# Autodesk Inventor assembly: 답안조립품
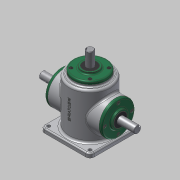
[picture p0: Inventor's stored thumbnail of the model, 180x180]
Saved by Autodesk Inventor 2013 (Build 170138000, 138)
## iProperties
Created: 2015-10
Part Number: 답안조립품
Document SubType Name: Assembly
Designer: user-11
Author: user-11
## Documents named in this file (14)
- C:\Users\user-11\Desktop\451007V1002\답안조립품.iam
- C:\Users\user-11\Desktop\451007V1002\본체.ipt
- C:\Users\user-11\Desktop\451007V1002\서브 베벨기어.ipt
- C:\Users\user-11\Desktop\451007V1002\서브 축.ipt
- 서브 축.ipt
- C:\Users\user-11\Desktop\451007V1002\오일실.ipt
- C:\Users\user-11\Desktop\451007V1002\커버.ipt
- C:\Users\user-11\Desktop\451007V1002\키 4x4.ipt
- C:\Users\user-11\Desktop\451007V1002\키 5x5.ipt
- C:\Users\user-11\Desktop\451007V1002\M4.ipt
- C:\Users\user-11\Desktop\451007V1002\메인 베벨기어.ipt
- C:\Users\user-11\Desktop\451007V1002\메인 축.ipt
- 메인 축.ipt
- C:\Users\user-11\Desktop\451007V1002\베어링 6203.ipt
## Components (12 placed, 1 different names)
1. M4:2
2. M4:3
3. M4:4
4. M4:5
5. M4:6
6. M4:7
7. M4:8
8. M4:9
9. M4:10
10. M4:11
11. M4:12
12. M4:13
